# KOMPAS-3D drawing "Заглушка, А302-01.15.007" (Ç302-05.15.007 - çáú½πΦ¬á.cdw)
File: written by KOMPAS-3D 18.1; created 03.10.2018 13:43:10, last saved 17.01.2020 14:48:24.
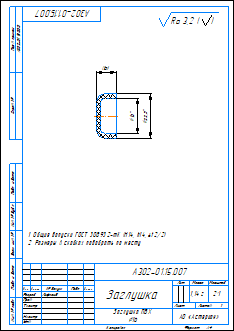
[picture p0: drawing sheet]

Sheet 1: A4, portrait

Document properties: Автор: Милов; Организация: Милов; Полное имя файла: D:\Мембранные насосы\Мембранный электропривод\А302-00.00.000 - ASTRA-302 (МЭ200)\А302-05.00.000 - Мембранный насос ASTRA-302-PVC\А302-05.15.007 - Заглушка.cdw; Масса: 0.00113785

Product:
- Part/product: Заглушка  | designation А302-01.15.007
    Масса: 0.00113785
    Раздел спецификации: Детали
    Форматы листов документа: A4
    source file: ..\3Д ПВХ\А302-01.15.007 - Заглушка.cdw
- Part/product: Заглушка  | designation А302-03.15.007
    Масса: 0.00340597
    Раздел спецификации: Детали
    Форматы листов документа: A4
    source file: ..\Чертежи Полипропилен\А302-03.15.007 - Заглушка.cdw

Title block, sheet 1: Наименование: Заглушка; designation: А302-01.15.007; Материал: Заглушка ПВХ; Масса: 1,14 г; scale: 2:1; Количество листов документа: 1; organisation: АО «Астерион»; Форматы листов документа: A4; stored path: \\192.168.87.28\Konstructor_doc\Мембранные насосы\Мембранный электропривод\А302-00.00.000 - ASTRA-302 (МЭ200)\3Д ПВХ\А302-01.15.007 - Заглушка.cdw; Разработал: Лифлянд

Views: Вид 1, Местный разрез 1, Спереди, Проекционный вид 2
Referenced files in D:\Мембранные насосы\Мембранный электропривод\А302-00.00.000 - ASTRA-302 (МЭ200)\3Д ПВХ\: А302-01.15.007 - Заглушка.m3d
Referenced files in Z:\Мембранные насосы\Мембранный электропривод\А302-00.00.000 - ASTRA-302 (МЭ200)\3Д ПВХ\: А302-01.15.007 - Заглушка.m3d
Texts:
  Ra 3,2
  Ra 3,2 ( )
Dimensions and other numbers on the sheet: 10; 16; 22,5; 2:1; 1; 1,14 г

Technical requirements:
  Общие допуски ГОСТ 30893.2-mK (H14, h14,  t2/2).
  Размеры в скобках подобрать по месту.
